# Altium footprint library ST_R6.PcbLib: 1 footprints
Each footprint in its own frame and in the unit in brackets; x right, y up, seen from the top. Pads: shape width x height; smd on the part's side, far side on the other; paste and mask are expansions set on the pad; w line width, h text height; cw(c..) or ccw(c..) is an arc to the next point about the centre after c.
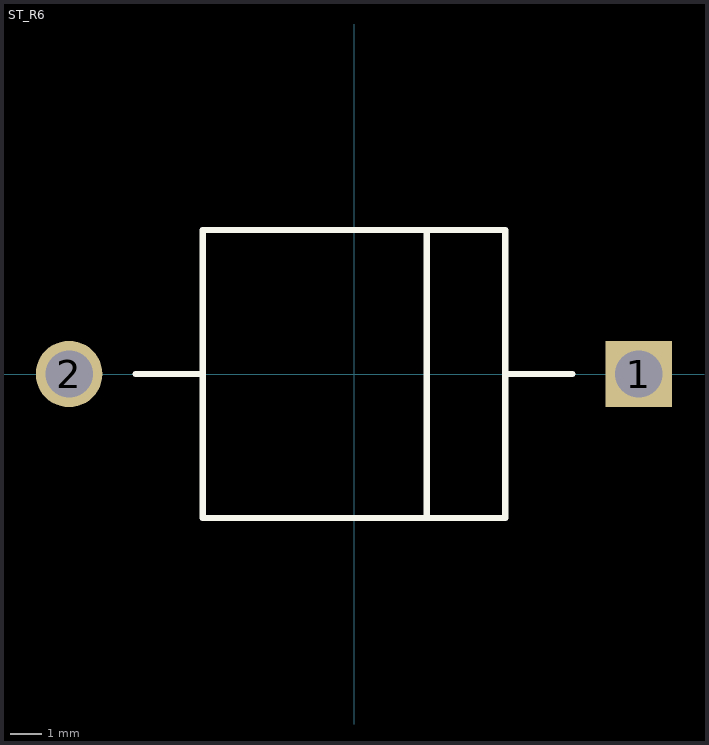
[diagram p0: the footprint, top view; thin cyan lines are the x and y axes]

## ST_R6 [mm]
pads (2):
  rect 2.1x2.1 hole 1.5: 1(9,0)
  round 2.1 hole 1.5: 2(-9,0)
Top Overlay:
  lines w0.2: -6.9,0 -4.775,0 ; 2.297,-4.55 2.297,4.55 ; 4.775,0 6.9,0 ; -4.775,0 -4.775,-4.55 4.775,-4.55 4.775,4.55 -4.775,4.55 -4.775,0
3D body "ST_R6.step": height 9.1, standoff 0, extent -4.55,-4.55 4.55,4.55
